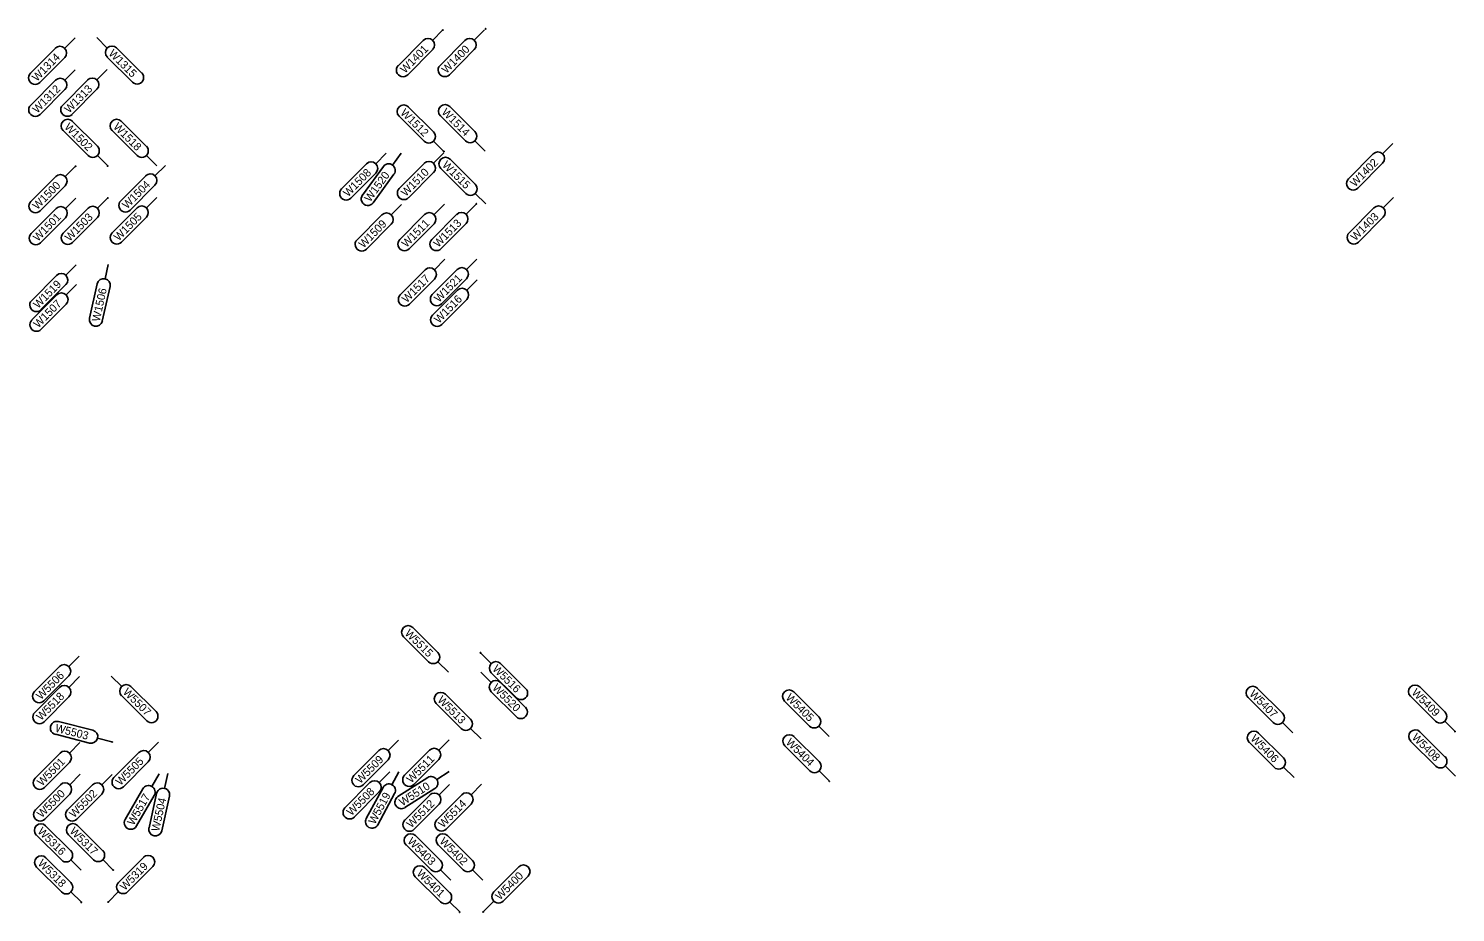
# Model space of a CAD drawing. Extents: x 12479652 to 12487250, y 9842710 to 9846560.
# Drawn here: x 12482280 to 12482502.8, y 9842722.6 to 9842860.7 of the extents above; entities that cross this region are included whole.
import ezdxf

# ---------------------------------------------------------------- set-up
doc = ezdxf.new("R2010")
doc.units = 0
doc.layers.add('_CIVIL_CONSTRUCTION', color=7, linetype='Continuous')
doc.layers.add('TextAlignmentLrg', color=7, linetype='Continuous')

msp = doc.modelspace()

# ---------------------------------------------------------------- linework, layer by layer
at = {"layer": '_CIVIL_CONSTRUCTION'}
for p, q in [((12482344.74, 9842860.46), (12482343.11, 9842858.82)), ((12482351.25, 9842860.46), (12482349.62, 9842858.83)), ((12482287.29, 9842859.23), (12482285.67, 9842857.6)), ((12482290.7, 9842859.25), (12482292.33, 9842857.63)), ((12482337.77, 9842854.91), (12482341.66, 9842858.82)), ((12482344.28, 9842854.91), (12482348.17, 9842858.82)), ((12482280.33, 9842853.68), (12482284.22, 9842857.59)), ((12482285.67, 9842856.15), (12482281.78, 9842852.23)), ((12482296.25, 9842852.29), (12482292.33, 9842856.18)), ((12482293.78, 9842857.64), (12482297.69, 9842853.75)), ((12482343.12, 9842857.37), (12482339.23, 9842853.46)), ((12482349.63, 9842857.38), (12482345.74, 9842853.46)), ((12482287.33, 9842854.23), (12482285.71, 9842852.6)), ((12482292.33, 9842854.27), (12482290.7, 9842852.64)), ((12482280.36, 9842848.68), (12482284.25, 9842852.59)), ((12482285.71, 9842851.15), (12482281.82, 9842847.23)), ((12482285.36, 9842848.72), (12482289.25, 9842852.63)), ((12482290.71, 9842851.18), (12482286.82, 9842847.27)), ((12482341.8, 9842843.08), (12482337.89, 9842846.97)), ((12482339.33, 9842848.42), (12482343.25, 9842844.53)), ((12482348.25, 9842843.13), (12482344.34, 9842847.02)), ((12482345.79, 9842848.47), (12482349.7, 9842844.58)), ((12482289.33, 9842840.84), (12482285.41, 9842844.73)), ((12482286.86, 9842846.19), (12482290.77, 9842842.3)), ((12482296.98, 9842840.85), (12482293.06, 9842844.74)), ((12482294.51, 9842846.19), (12482298.42, 9842842.31)), ((12482344.88, 9842841.46), (12482343.25, 9842843.08)), ((12482351.34, 9842841.51), (12482349.71, 9842843.13)), ((12482493.08, 9842842.73), (12482491.46, 9842841.1)), ((12482292.41, 9842839.22), (12482290.78, 9842840.84)), ((12482300.06, 9842839.23), (12482298.43, 9842840.85)), ((12482335.87, 9842841.18), (12482334.25, 9842839.55)), ((12482338.22, 9842841.2), (12482336.86, 9842839.34)), ((12482344.88, 9842841.25), (12482343.26, 9842839.62)), ((12482345.86, 9842840.26), (12482349.78, 9842836.37)), ((12482486.12, 9842837.18), (12482490.01, 9842841.09)), ((12482287.36, 9842839.19), (12482285.74, 9842837.56)), ((12482301.39, 9842839.3), (12482299.77, 9842837.67)), ((12482328.91, 9842835.63), (12482332.8, 9842839.55)), ((12482334.26, 9842838.1), (12482330.37, 9842834.19)), ((12482332.18, 9842834.66), (12482335.43, 9842839.12)), ((12482337.09, 9842837.91), (12482333.84, 9842833.45)), ((12482337.92, 9842835.7), (12482341.81, 9842839.61)), ((12482343.27, 9842838.17), (12482339.38, 9842834.25)), ((12482348.33, 9842834.91), (12482344.42, 9842838.8)), ((12482491.46, 9842839.64), (12482487.57, 9842835.73)), ((12482280.4, 9842833.64), (12482284.29, 9842837.56)), ((12482285.74, 9842836.11), (12482281.85, 9842832.2)), ((12482294.43, 9842833.75), (12482298.32, 9842837.67)), ((12482299.77, 9842836.22), (12482295.88, 9842832.31)), ((12482287.4, 9842834.19), (12482285.78, 9842832.56)), ((12482292.4, 9842834.23), (12482290.78, 9842832.6)), ((12482300.05, 9842834.29), (12482298.43, 9842832.66)), ((12482344.96, 9842833.25), (12482343.34, 9842831.62)), ((12482349.96, 9842833.28), (12482348.34, 9842831.65)), ((12482351.41, 9842833.29), (12482349.78, 9842834.92)), ((12482493.18, 9842834.3), (12482491.56, 9842832.67)), ((12482280.44, 9842828.64), (12482284.33, 9842832.56)), ((12482285.78, 9842831.11), (12482281.89, 9842827.2)), ((12482285.44, 9842828.68), (12482289.33, 9842832.6)), ((12482290.78, 9842831.15), (12482286.89, 9842827.24)), ((12482293.09, 9842828.74), (12482296.97, 9842832.66)), ((12482298.43, 9842831.21), (12482294.54, 9842827.3)), ((12482331.32, 9842827.64), (12482335.21, 9842831.55)), ((12482338.28, 9842833.19), (12482336.66, 9842831.56)), ((12482338, 9842827.7), (12482341.88, 9842831.61)), ((12482342.99, 9842827.74), (12482346.88, 9842831.65)), ((12482486.22, 9842828.75), (12482490.11, 9842832.67)), ((12482491.57, 9842831.22), (12482487.68, 9842827.31)), ((12482336.66, 9842830.11), (12482332.78, 9842826.19)), ((12482343.34, 9842830.17), (12482339.45, 9842826.25)), ((12482348.34, 9842830.2), (12482344.45, 9842826.29)), ((12482345.04, 9842824.62), (12482343.41, 9842822.98)), ((12482350.04, 9842824.66), (12482348.41, 9842823.03)), ((12482280.52, 9842818.2), (12482284.41, 9842822.11)), ((12482287.48, 9842823.75), (12482285.86, 9842822.12)), ((12482292.47, 9842823.82), (12482291.97, 9842821.58)), ((12482338.07, 9842819.07), (12482341.96, 9842822.98)), ((12482343.07, 9842819.11), (12482346.96, 9842823.02)), ((12482285.86, 9842820.67), (12482281.97, 9842816.76)), ((12482287.5, 9842820.69), (12482285.88, 9842819.05)), ((12482289.55, 9842815.41), (12482290.74, 9842820.8)), ((12482292.75, 9842820.35), (12482291.55, 9842814.97)), ((12482343.42, 9842821.53), (12482339.53, 9842817.62)), ((12482348.42, 9842821.58), (12482344.53, 9842817.66)), ((12482350.07, 9842821.43), (12482348.44, 9842819.8)), ((12482280.54, 9842815.14), (12482284.43, 9842819.05)), ((12482343.1, 9842815.88), (12482346.99, 9842819.8)), ((12482348.45, 9842818.35), (12482344.56, 9842814.44)), ((12482285.89, 9842817.6), (12482282, 9842813.69)), ((12482340.03, 9842767.1), (12482343.94, 9842763.21)), ((12482342.5, 9842761.75), (12482338.58, 9842765.64)), ((12482287.93, 9842762.63), (12482286.31, 9842761)), ((12482350.65, 9842763.09), (12482352.28, 9842761.47)), ((12482280.97, 9842757.08), (12482284.86, 9842760.99)), ((12482345.58, 9842760.13), (12482343.95, 9842761.76)), ((12482350.63, 9842760.13), (12482352.26, 9842758.51)), ((12482356.2, 9842756.13), (12482352.29, 9842760.02)), ((12482353.73, 9842761.47), (12482357.65, 9842757.58)), ((12482280.99, 9842753.82), (12482284.88, 9842757.73)), ((12482286.31, 9842759.55), (12482282.42, 9842755.63)), ((12482288, 9842759.42), (12482286.33, 9842757.74)), ((12482292.93, 9842759.49), (12482294.57, 9842757.87)), ((12482296.02, 9842757.87), (12482299.93, 9842753.98)), ((12482353.71, 9842758.51), (12482357.62, 9842754.62)), ((12482471.9, 9842757.61), (12482475.82, 9842753.72)), ((12482497.25, 9842757.81), (12482501.17, 9842753.92)), ((12482286.34, 9842756.29), (12482282.45, 9842752.37)), ((12482298.48, 9842752.53), (12482294.57, 9842756.42)), ((12482345.13, 9842756.67), (12482349.04, 9842752.78)), ((12482356.18, 9842753.17), (12482352.26, 9842757.06)), ((12482401.98, 9842751.7), (12482398.06, 9842755.59)), ((12482399.51, 9842757.04), (12482403.42, 9842753.15)), ((12482474.37, 9842752.27), (12482470.46, 9842756.15)), ((12482499.72, 9842752.46), (12482495.81, 9842756.35)), ((12482347.59, 9842751.32), (12482343.68, 9842755.21)), ((12482284.72, 9842752.4), (12482290.07, 9842751.04)), ((12482350.68, 9842749.71), (12482349.04, 9842751.33)), ((12482405.06, 9842750.08), (12482403.43, 9842751.7)), ((12482477.45, 9842750.65), (12482475.82, 9842752.27)), ((12482497.29, 9842750.81), (12482501.2, 9842746.92)), ((12482502.8, 9842750.85), (12482501.17, 9842752.47)), ((12482289.57, 9842749.05), (12482284.22, 9842750.41)), ((12482288.03, 9842749.12), (12482286.41, 9842747.48)), ((12482293.04, 9842749.23), (12482290.81, 9842749.79)), ((12482300.34, 9842749.21), (12482298.71, 9842747.58)), ((12482337.79, 9842749.51), (12482336.17, 9842747.87)), ((12482345.72, 9842749.57), (12482344.09, 9842747.94)), ((12482402.02, 9842744.7), (12482398.11, 9842748.59)), ((12482399.56, 9842750.04), (12482403.47, 9842746.15)), ((12482474.55, 9842745.27), (12482470.64, 9842749.16)), ((12482472.08, 9842750.61), (12482476, 9842746.72)), ((12482499.76, 9842745.46), (12482495.84, 9842749.35)), ((12482281.07, 9842743.57), (12482284.96, 9842747.48)), ((12482293.37, 9842743.66), (12482297.26, 9842747.58)), ((12482330.83, 9842743.96), (12482334.72, 9842747.87)), ((12482336.17, 9842746.42), (12482332.28, 9842742.51)), ((12482338.75, 9842744.02), (12482342.64, 9842747.93)), ((12482344.1, 9842746.49), (12482340.21, 9842742.57)), ((12482286.42, 9842746.03), (12482282.53, 9842742.12)), ((12482288.07, 9842744.17), (12482286.45, 9842742.53)), ((12482293.07, 9842744.16), (12482291.45, 9842742.52)), ((12482298.72, 9842746.13), (12482294.83, 9842742.22)), ((12482300.42, 9842744.26), (12482299.27, 9842742.27)), ((12482301.76, 9842744.27), (12482301.25, 9842741.96)), ((12482336.45, 9842744.54), (12482334.78, 9842742.86)), ((12482337.87, 9842744.56), (12482336.78, 9842742.53)), ((12482345.71, 9842744.58), (12482343.77, 9842743.34)), ((12482405.11, 9842743.08), (12482403.48, 9842744.7)), ((12482477.63, 9842743.65), (12482476, 9842745.27)), ((12482502.84, 9842743.85), (12482501.21, 9842745.47)), ((12482281.11, 9842738.62), (12482285, 9842742.53)), ((12482286.11, 9842738.61), (12482290, 9842742.52)), ((12482295.11, 9842737.12), (12482297.87, 9842741.9)), ((12482329.44, 9842738.95), (12482333.33, 9842742.86)), ((12482332.76, 9842737.26), (12482335.39, 9842742.12)), ((12482337.71, 9842740.69), (12482342.36, 9842743.65)), ((12482343.46, 9842741.93), (12482338.81, 9842738.96)), ((12482345.74, 9842742.57), (12482344.12, 9842740.94)), ((12482350.74, 9842742.61), (12482349.12, 9842740.98)), ((12482286.46, 9842741.08), (12482282.57, 9842737.17)), ((12482291.46, 9842741.07), (12482287.57, 9842737.16)), ((12482299.65, 9842740.87), (12482296.89, 9842736.09)), ((12482298.84, 9842735.79), (12482300.02, 9842741.18)), ((12482302.03, 9842740.74), (12482300.84, 9842735.35)), ((12482334.79, 9842741.41), (12482330.9, 9842737.5)), ((12482337.19, 9842741.14), (12482334.57, 9842736.29)), ((12482338.78, 9842737.02), (12482342.67, 9842740.93)), ((12482343.78, 9842737.06), (12482347.67, 9842740.97)), ((12482344.12, 9842739.49), (12482340.23, 9842735.57)), ((12482349.12, 9842739.52), (12482345.23, 9842735.61)), ((12482282.69, 9842736.13), (12482286.6, 9842732.24)), ((12482287.69, 9842736.17), (12482291.6, 9842732.28)), ((12482285.16, 9842730.78), (12482281.25, 9842734.67)), ((12482290.16, 9842730.82), (12482286.25, 9842734.71)), ((12482342.9, 9842729.24), (12482338.98, 9842733.13)), ((12482340.43, 9842734.58), (12482344.34, 9842730.69)), ((12482347.9, 9842729.24), (12482343.98, 9842733.13)), ((12482345.43, 9842734.58), (12482349.34, 9842730.69)), ((12482282.73, 9842731.13), (12482286.64, 9842727.24)), ((12482288.24, 9842729.17), (12482286.61, 9842730.79)), ((12482293.24, 9842729.21), (12482291.61, 9842730.83)), ((12482294.09, 9842727.28), (12482297.98, 9842731.19)), ((12482285.2, 9842725.78), (12482281.28, 9842729.67)), ((12482299.43, 9842729.75), (12482295.54, 9842725.84)), ((12482341.87, 9842729.59), (12482345.78, 9842725.7)), ((12482345.98, 9842727.62), (12482344.35, 9842729.24)), ((12482350.98, 9842727.62), (12482349.35, 9842729.24)), ((12482352.69, 9842725.79), (12482356.58, 9842729.7)), ((12482344.33, 9842724.25), (12482340.42, 9842728.14)), ((12482358.04, 9842728.26), (12482354.15, 9842724.34)), ((12482288.28, 9842724.17), (12482286.65, 9842725.79)), ((12482292.47, 9842724.2), (12482294.09, 9842725.83)), ((12482347.41, 9842722.63), (12482345.78, 9842724.25)), ((12482351.07, 9842722.71), (12482352.7, 9842724.34))]:
    msp.add_line(p, q, dxfattribs=at)
for centre, start, end in [((12482284.94, 9842856.87), 315.1702, 135.1702), ((12482293.06, 9842856.91), 45.1702, 225.1702), ((12482342.39, 9842858.1), 315.1702, 135.1702), ((12482348.9, 9842858.1), 315.1702, 135.1702), ((12482281.05, 9842852.96), 135.1702, 315.1702), ((12482296.97, 9842853.02), 225.1702, 45.1702), ((12482338.5, 9842854.18), 135.1702, 315.1702), ((12482345.01, 9842854.19), 135.1702, 315.1702), ((12482284.98, 9842851.87), 315.1702, 135.1702), ((12482289.98, 9842851.91), 315.1702, 135.1702), ((12482281.09, 9842847.96), 135.1702, 315.1702), ((12482286.09, 9842847.99), 135.1702, 315.1702), ((12482338.61, 9842847.7), 45.1702, 225.1702), ((12482345.06, 9842847.75), 45.1702, 225.1702), ((12482286.14, 9842845.46), 45.1702, 225.1702), ((12482293.79, 9842845.47), 45.1702, 225.1702), ((12482342.52, 9842843.81), 225.1702, 45.1702), ((12482348.98, 9842843.86), 225.1702, 45.1702), ((12482290.05, 9842841.57), 225.1702, 45.1702), ((12482297.7, 9842841.58), 225.1702, 45.1702), ((12482342.54, 9842838.89), 315.1702, 135.1702), ((12482345.14, 9842839.53), 45.1702, 225.1702), ((12482490.74, 9842840.37), 315.1702, 135.1702), ((12482285.01, 9842836.83), 315.1702, 135.1702), ((12482299.04, 9842836.94), 315.1702, 135.1702), ((12482333.53, 9842838.82), 315.1702, 135.1702), ((12482336.26, 9842838.51), 323.8955, 143.8955), ((12482329.64, 9842834.91), 135.1702, 315.1702), ((12482338.65, 9842834.98), 135.1702, 315.1702), ((12482349.05, 9842835.64), 225.1702, 45.1702), ((12482486.85, 9842836.45), 135.1702, 315.1702), ((12482281.12, 9842832.92), 135.1702, 315.1702), ((12482295.15, 9842833.03), 135.1702, 315.1702), ((12482333.01, 9842834.06), 143.8955, 323.8955), ((12482285.05, 9842831.83), 315.1702, 135.1702), ((12482290.05, 9842831.87), 315.1702, 135.1702), ((12482297.7, 9842831.93), 315.1702, 135.1702), ((12482335.94, 9842830.83), 315.1702, 135.1702), ((12482342.61, 9842830.89), 315.1702, 135.1702), ((12482347.61, 9842830.92), 315.1702, 135.1702), ((12482490.84, 9842831.94), 315.1702, 135.1702), ((12482281.16, 9842827.92), 135.1702, 315.1702), ((12482286.16, 9842827.96), 135.1702, 315.1702), ((12482293.81, 9842828.02), 135.1702, 315.1702), ((12482332.05, 9842826.92), 135.1702, 315.1702), ((12482338.72, 9842826.98), 135.1702, 315.1702), ((12482343.72, 9842827.01), 135.1702, 315.1702), ((12482486.95, 9842828.03), 135.1702, 315.1702), ((12482285.13, 9842821.39), 315.1702, 135.1702), ((12482342.69, 9842822.26), 315.1702, 135.1702), ((12482347.69, 9842822.3), 315.1702, 135.1702), ((12482291.75, 9842820.58), 347.4883, 167.4883), ((12482347.72, 9842819.07), 315.1702, 135.1702), ((12482281.25, 9842817.48), 135.1702, 315.1702), ((12482285.16, 9842818.33), 315.1702, 135.1702), ((12482338.8, 9842818.34), 135.1702, 315.1702), ((12482343.8, 9842818.39), 135.1702, 315.1702), ((12482290.55, 9842815.19), 167.4883, 347.4883), ((12482343.83, 9842815.16), 135.1702, 315.1702), ((12482281.27, 9842814.41), 135.1702, 315.1702), ((12482339.31, 9842766.37), 45.1702, 225.1702), ((12482343.22, 9842762.48), 225.1702, 45.1702), ((12482285.58, 9842760.27), 315.1702, 135.1702), ((12482353.01, 9842760.75), 45.1702, 225.1702), ((12482285.61, 9842757.01), 315.1702, 135.1702), ((12482295.29, 9842757.15), 45.1702, 225.1702), ((12482352.99, 9842757.79), 45.1702, 225.1702), ((12482356.92, 9842756.86), 225.1702, 45.1702), ((12482471.18, 9842756.88), 45.1702, 225.1702), ((12482496.53, 9842757.08), 45.1702, 225.1702), ((12482281.69, 9842756.36), 135.1702, 315.1702), ((12482344.4, 9842755.94), 45.1702, 225.1702), ((12482398.79, 9842756.32), 45.1702, 225.1702), ((12482281.72, 9842753.1), 135.1702, 315.1702), ((12482299.21, 9842753.26), 225.1702, 45.1702), ((12482356.9, 9842753.9), 225.1702, 45.1702), ((12482402.7, 9842752.43), 225.1702, 45.1702), ((12482475.09, 9842752.99), 225.1702, 45.1702), ((12482500.44, 9842753.19), 225.1702, 45.1702), ((12482284.47, 9842751.4), 75.7512, 255.7512), ((12482289.82, 9842750.05), 255.7512, 75.7512), ((12482348.32, 9842752.05), 225.1702, 45.1702), ((12482471.36, 9842749.88), 45.1702, 225.1702), ((12482496.57, 9842750.08), 45.1702, 225.1702), ((12482398.84, 9842749.32), 45.1702, 225.1702), ((12482285.69, 9842746.76), 315.1702, 135.1702), ((12482297.99, 9842746.85), 315.1702, 135.1702), ((12482335.45, 9842747.15), 315.1702, 135.1702), ((12482343.37, 9842747.21), 315.1702, 135.1702), ((12482475.27, 9842745.99), 225.1702, 45.1702), ((12482500.48, 9842746.19), 225.1702, 45.1702), ((12482402.75, 9842745.43), 225.1702, 45.1702), ((12482281.8, 9842742.84), 135.1702, 315.1702), ((12482285.73, 9842741.81), 315.1702, 135.1702), ((12482290.73, 9842741.8), 315.1702, 135.1702), ((12482294.1, 9842742.94), 135.1702, 315.1702), ((12482298.76, 9842741.38), 329.9827, 149.9827), ((12482301.03, 9842740.96), 347.5584, 167.5584), ((12482331.56, 9842743.23), 135.1702, 315.1702), ((12482334.06, 9842742.14), 315.1702, 135.1702), ((12482336.29, 9842741.63), 331.6177, 151.6177), ((12482339.48, 9842743.3), 135.1702, 315.1702), ((12482342.91, 9842742.79), 302.5437, 122.5437), ((12482338.26, 9842739.82), 122.5437, 302.5437), ((12482343.4, 9842740.21), 315.1702, 135.1702), ((12482348.4, 9842740.25), 315.1702, 135.1702), ((12482281.84, 9842737.89), 135.1702, 315.1702), ((12482286.84, 9842737.88), 135.1702, 315.1702), ((12482330.17, 9842738.22), 135.1702, 315.1702), ((12482281.97, 9842735.4), 45.1702, 225.1702), ((12482286.97, 9842735.44), 45.1702, 225.1702), ((12482296, 9842736.61), 149.9827, 329.9827), ((12482299.84, 9842735.57), 167.5584, 347.5584), ((12482333.67, 9842736.78), 151.6177, 331.6177), ((12482339.51, 9842736.3), 135.1702, 315.1702), ((12482344.51, 9842736.33), 135.1702, 315.1702), ((12482339.71, 9842733.85), 45.1702, 225.1702), ((12482344.71, 9842733.85), 45.1702, 225.1702), ((12482282.01, 9842730.4), 45.1702, 225.1702), ((12482285.88, 9842731.51), 225.1702, 45.1702), ((12482290.88, 9842731.55), 225.1702, 45.1702), ((12482298.7, 9842730.47), 315.1702, 135.1702), ((12482341.14, 9842728.86), 45.1702, 225.1702), ((12482343.62, 9842729.96), 225.1702, 45.1702), ((12482348.62, 9842729.96), 225.1702, 45.1702), ((12482357.31, 9842728.98), 315.1702, 135.1702), ((12482285.92, 9842726.51), 225.1702, 45.1702), ((12482294.81, 9842726.56), 135.1702, 315.1702), ((12482345.06, 9842724.97), 225.1702, 45.1702), ((12482353.42, 9842725.07), 135.1702, 315.1702)]:
    msp.add_arc(centre, 1.03, start, end, dxfattribs=at)
at = {"layer": 'TextAlignmentLrg'}
for centre in [(12482344.71, 9842860.43), (12482351.41, 9842860.62), (12482344.88, 9842841.46), (12482287.38, 9842839.16), (12482292.38, 9842839.2), (12482292.42, 9842834.2), (12482349.96, 9842833.28), (12482350.6, 9842763.14), (12482502.75, 9842750.85), (12482293.08, 9842749.21), (12482405.06, 9842743.08), (12482293.24, 9842729.21), (12482288.28, 9842724.17), (12482292.47, 9842724.2), (12482347.36, 9842722.63), (12482351.02, 9842722.66)]:
    msp.add_circle(centre, 0.05, dxfattribs=at)

# ---------------------------------------------------------------- texts
at = {"layer": '_CIVIL_CONSTRUCTION'}
for s, rotation, p in [('W1401', 45.1702, (12482338.81, 9842853.59)), ('W1400', 45.1702, (12482345.28, 9842853.56)), ('W1314', 45.1702, (12482281.32, 9842852.32)), ('W1315', 315.1702, (12482292.43, 9842856.66)), ('W1312', 45.1702, (12482281.38, 9842847.35)), ('W1313', 45.1702, (12482286.37, 9842847.37)), ('W1512', 315.1702, (12482338, 9842847.4)), ('W1514', 315.1702, (12482344.43, 9842847.48)), ('W1502', 315.1702, (12482285.53, 9842845.17)), ('W1518', 315.1702, (12482293.16, 9842845.2)), ('W1515', 315.1702, (12482344.52, 9842839.24)), ('W1402', 45.1702, (12482487.14, 9842835.85)), ('W1508', 45.1702, (12482329.91, 9842834.28)), ('W1520', 53.8955, (12482333.37, 9842833.48)), ('W1510', 45.1702, (12482338.92, 9842834.35)), ('W1500', 45.1702, (12482281.4, 9842832.29)), ('W1504', 45.1702, (12482295.42, 9842832.4)), ('W1501', 45.1702, (12482281.47, 9842827.33)), ('W1503', 45.1702, (12482286.44, 9842827.34)), ('W1505', 45.1702, (12482294.1, 9842827.4)), ('W1403', 45.1702, (12482487.23, 9842827.41)), ('W1509', 45.1702, (12482332.32, 9842826.29)), ('W1511', 45.1702, (12482339.03, 9842826.38)), ('W1513', 45.1702, (12482344, 9842826.39)), ('W1517', 45.1702, (12482339.08, 9842817.73)), ('W1521', 45.1702, (12482344.11, 9842817.8)), ('W1519', 45.1702, (12482281.52, 9842816.85)), ('W1506', 77.4883, (12482291.12, 9842814.8)), ('W1507', 45.1702, (12482281.55, 9842813.8)), ('W1516', 45.1702, (12482344.1, 9842814.53)), ('W5515', 315.1702, (12482338.69, 9842766.09)), ('W5506', 45.1702, (12482281.96, 9842755.73)), ('W5516', 315.1702, (12482352.37, 9842760.52)), ('W5507', 315.1702, (12482294.67, 9842756.9)), ('W5520', 315.1702, (12482352.35, 9842757.55)), ('W5407', 315.1702, (12482470.56, 9842756.6)), ('W5409', 315.1702, (12482495.9, 9842756.81)), ('W5518', 45.1702, (12482281.99, 9842752.47)), ('W5513', 315.1702, (12482343.78, 9842755.66)), ('W5405', 315.1702, (12482398.17, 9842756.03)), ('W5503', 345.7512, (12482284.08, 9842750.85)), ('W5404', 315.1702, (12482398.2, 9842749.05)), ('W5406', 315.1702, (12482470.73, 9842749.61)), ('W5408', 315.1702, (12482495.94, 9842749.81)), ('W5501', 45.1702, (12482282.11, 9842742.25)), ('W5505', 45.1702, (12482294.38, 9842742.33)), ('W5509', 45.1702, (12482331.83, 9842742.61)), ('W5511', 45.1702, (12482339.79, 9842742.7)), ('W5508', 45.1702, (12482330.44, 9842737.6)), ('W5510', 32.5437, (12482338.38, 9842739.15)), ('W5500', 45.1702, (12482282.11, 9842737.27)), ('W5502', 45.1702, (12482287.13, 9842737.28)), ('W5517', 59.9827, (12482296.43, 9842736.08)), ('W5504', 77.5584, (12482300.4, 9842735.17)), ('W5519', 61.6177, (12482334.11, 9842736.25)), ('W5512', 45.1702, (12482339.8, 9842735.69)), ('W5514', 45.1702, (12482344.77, 9842735.7)), ('W5316', 315.1702, (12482281.34, 9842735.13)), ('W5317', 315.1702, (12482286.35, 9842735.16)), ('W5403', 315.1702, (12482339.09, 9842733.57)), ('W5402', 315.1702, (12482344.1, 9842733.56)), ('W5318', 315.1702, (12482281.38, 9842730.13)), ('W5319', 45.1702, (12482295.05, 9842725.92)), ('W5401', 315.1702, (12482340.55, 9842728.56)), ('W5400', 45.1702, (12482353.65, 9842724.43))]:
    msp.add_text(s, height=1.25, rotation=rotation, dxfattribs=at).set_placement(p)

doc.saveas('drawing.dxf')
